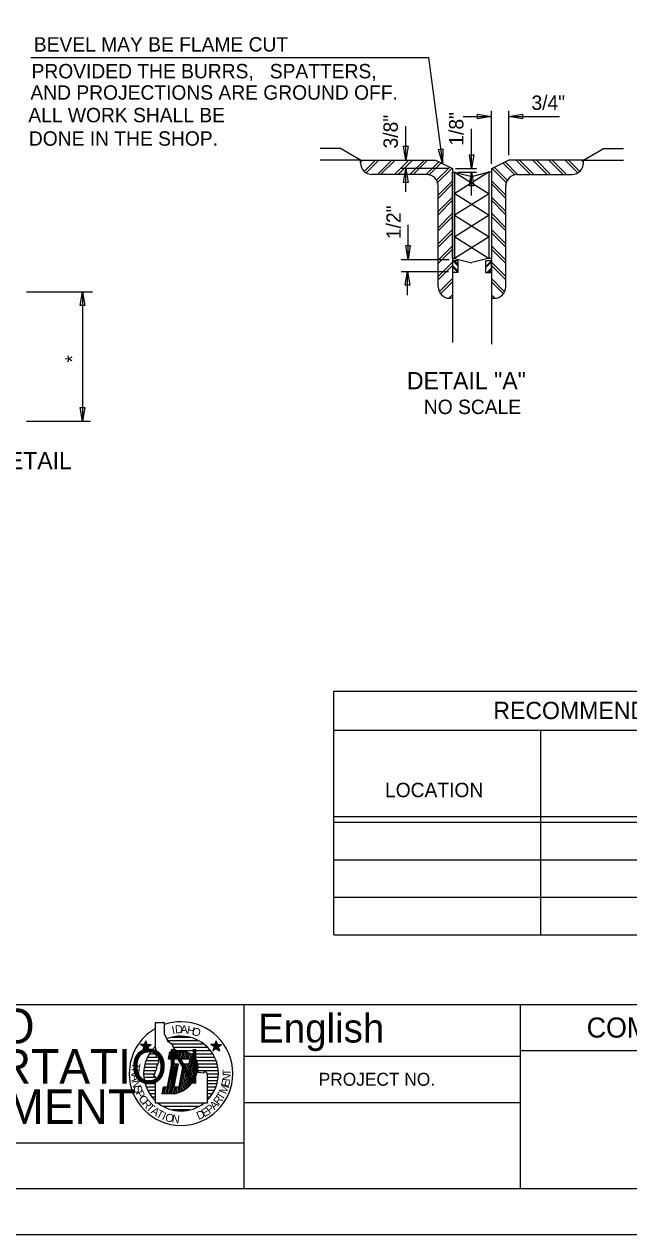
# Model space of a CAD drawing. Extents: x 0 to 11.3, y 0 to 7.9.
# Drawn here: x 5.619 to 7.81, y 0 to 4.38 of the extents above; entities that cross this region are included whole.
import ezdxf

# ---------------------------------------------------------------- set-up
doc = ezdxf.new("R2010")
doc.units = 0
for name, color, linetype in [('BORDER_ANNO_Cutsheet', 7, 'Continuous'), ('BRDG_ANNO_Anno-Sheet', 7, 'Continuous'), ('BRDG_ANNO_General-Notes', 7, 'Continuous'), ('BRDG_BASE_Obj-Line', 7, 'Continuous'), ('BRDG_BASE_Pattern', 7, 'Continuous')]:
    doc.layers.add(name, color=color, linetype=linetype)

msp = doc.modelspace()

# ---------------------------------------------------------------- linework, layer by layer
at = {"layer": 'BORDER_ANNO_Cutsheet'}
msp.add_lwpolyline([(0, 7.3333), (11.3333, 7.3333), (11.3333, 0), (0, 0)], close=True, dxfattribs=at)
at = {"layer": 'BRDG_ANNO_Anno-Sheet'}
for p, q in [((0.5, 0.8333), (6.4167, 0.8333)), ((6.4167, 0.1667), (6.4167, 0.8333)), ((6.4167, 0.8333), (11.1667, 0.8333)), ((7.4167, 0.1667), (7.4167, 0.8333)), ((6.0948, 0.6808), (6.0948, 0.7677)), ((6.0948, 0.7677), (6.1277, 0.7677)), ((6.1277, 0.7244), (6.1277, 0.7677)), ((6.0552, 0.6885), (6.0598, 0.7023)), ((6.0598, 0.6746), (6.0598, 0.7023)), ((6.0644, 0.6885), (6.0598, 0.7023)), ((6.1277, 0.7244), (6.1365, 0.7087)), ((6.1365, 0.7087), (6.1381, 0.7017)), ((6.1381, 0.7017), (6.1554, 0.6896)), ((6.139, 0.7027), (6.2502, 0.7027)), ((6.155, 0.7148), (6.2194, 0.7148)), ((6.3106, 0.6885), (6.3152, 0.7023)), ((6.3152, 0.6746), (6.3152, 0.7023)), ((6.3198, 0.6885), (6.3152, 0.7023)), ((6.0671, 0.68), (6.0408, 0.6885)), ((6.0552, 0.6885), (6.0408, 0.6885)), ((6.0525, 0.68), (6.0408, 0.6885)), ((6.0644, 0.6885), (6.0479, 0.666)), ((6.0525, 0.68), (6.0479, 0.666)), ((6.0598, 0.6746), (6.0479, 0.666)), ((6.0525, 0.68), (6.079, 0.6885)), ((6.0552, 0.6885), (6.0717, 0.666)), ((6.0598, 0.6746), (6.0717, 0.666)), ((6.0644, 0.6885), (6.079, 0.6885)), ((6.0671, 0.68), (6.079, 0.6885)), ((6.0671, 0.68), (6.0717, 0.666)), ((6.0806, 0.6669), (6.0979, 0.6669)), ((6.0915, 0.6787), (6.0954, 0.6787)), ((6.0981, 0.6687), (6.0948, 0.6808)), ((6.0981, 0.6583), (6.0981, 0.6687)), ((6.0981, 0.6496), (6.0981, 0.6583)), ((6.1417, 0.6356), (6.1469, 0.6619)), ((6.1465, 0.6356), (6.1513, 0.6619)), ((6.1469, 0.6619), (6.2042, 0.6619)), ((6.1517, 0.6356), (6.1567, 0.6619)), ((6.155, 0.6908), (6.269, 0.6908)), ((6.1554, 0.6896), (6.1608, 0.6756)), ((6.1571, 0.6356), (6.1619, 0.6619)), ((6.1596, 0.6787), (6.2835, 0.6787)), ((6.1608, 0.6756), (6.1781, 0.6619)), ((6.1623, 0.6356), (6.1673, 0.6619)), ((6.1675, 0.6356), (6.1725, 0.6619)), ((6.1719, 0.6669), (6.2942, 0.6669)), ((6.1729, 0.6356), (6.1777, 0.6619)), ((6.1781, 0.6356), (6.1831, 0.6619)), ((6.1835, 0.6356), (6.1883, 0.6619)), ((6.1887, 0.6356), (6.1937, 0.6619)), ((6.1942, 0.6356), (6.199, 0.6619)), ((6.1994, 0.6356), (6.2044, 0.6619)), ((6.2046, 0.6356), (6.2094, 0.6604)), ((6.21, 0.6356), (6.2144, 0.659)), ((6.3225, 0.68), (6.296, 0.6885)), ((6.3079, 0.68), (6.296, 0.6885)), ((6.3106, 0.6885), (6.296, 0.6885)), ((6.3198, 0.6885), (6.3033, 0.666)), ((6.3079, 0.68), (6.3033, 0.666)), ((6.3152, 0.6746), (6.3033, 0.666)), ((6.3079, 0.68), (6.3342, 0.6885)), ((6.3106, 0.6885), (6.3271, 0.666)), ((6.3152, 0.6746), (6.3271, 0.666)), ((6.3198, 0.6885), (6.3342, 0.6885)), ((6.3225, 0.68), (6.3342, 0.6885)), ((6.3225, 0.68), (6.3271, 0.666)), ((7.4167, 0.6667), (10.0833, 0.6667)), ((6.0569, 0.6188), (6.1037, 0.6188)), ((6.0604, 0.6308), (6.1063, 0.6308)), ((6.0656, 0.6427), (6.0994, 0.6427)), ((6.0723, 0.6548), (6.0975, 0.6548)), ((6.1, 0.6427), (6.0981, 0.6496)), ((6.1069, 0.6392), (6.1, 0.6427)), ((6.1, 0.6096), (6.1033, 0.6167)), ((6.1033, 0.6167), (6.1069, 0.6252)), ((6.1069, 0.6304), (6.1069, 0.6392)), ((6.1069, 0.6252), (6.1069, 0.6304)), ((6.1381, 0.535), (6.1537, 0.6183)), ((6.1387, 0.5106), (6.159, 0.6183)), ((6.2204, 0.6356), (6.1417, 0.6356)), ((6.1442, 0.5106), (6.1644, 0.6183)), ((6.1494, 0.5106), (6.1696, 0.6183)), ((6.1537, 0.6183), (6.1767, 0.6183)), ((6.1548, 0.5106), (6.175, 0.6183)), ((6.1767, 0.6183), (6.161, 0.535)), ((6.1812, 0.535), (6.1969, 0.6183)), ((6.1823, 0.5158), (6.2015, 0.6183)), ((6.1879, 0.5183), (6.2067, 0.6183)), ((6.1937, 0.521), (6.2121, 0.6183)), ((6.1969, 0.6183), (6.2173, 0.6183)), ((6.1998, 0.5248), (6.224, 0.654)), ((6.2058, 0.5285), (6.2287, 0.6506)), ((6.2121, 0.5335), (6.2331, 0.6462)), ((6.2152, 0.6356), (6.2192, 0.6567)), ((6.2173, 0.6183), (6.2204, 0.6356)), ((6.2185, 0.5396), (6.2375, 0.6415)), ((6.2229, 0.6548), (6.3025, 0.6548)), ((6.2252, 0.5467), (6.2417, 0.6354)), ((6.2323, 0.5563), (6.2456, 0.6273)), ((6.2367, 0.6427), (6.3092, 0.6427)), ((6.2406, 0.5725), (6.2485, 0.615)), ((6.2442, 0.6308), (6.3144, 0.6308)), ((6.2481, 0.6188), (6.3181, 0.6188)), ((6.4167, 0.6458), (7.4167, 0.6458)), ((6.0521, 0.5827), (6.0925, 0.5827)), ((6.0525, 0.5948), (6.0969, 0.5948)), ((6.0527, 0.5708), (6.0938, 0.5708)), ((6.0542, 0.6069), (6.0994, 0.6069)), ((6.0896, 0.575), (6.0929, 0.5835)), ((6.0948, 0.5698), (6.0896, 0.575)), ((6.0929, 0.5835), (6.0948, 0.5906)), ((6.0948, 0.5906), (6.1, 0.601)), ((6.0981, 0.5646), (6.0948, 0.5698)), ((6.1, 0.601), (6.1, 0.6096)), ((6.2469, 0.5925), (6.2494, 0.5887)), ((6.2475, 0.5948), (6.3225, 0.5948)), ((6.2492, 0.6069), (6.3208, 0.6069)), ((6.2494, 0.5887), (6.2598, 0.5871)), ((6.2598, 0.5871), (6.2702, 0.5854)), ((6.2702, 0.5854), (6.2754, 0.5923)), ((6.2754, 0.5923), (6.2823, 0.5819)), ((6.2817, 0.5827), (6.3229, 0.5827)), ((6.2823, 0.5819), (6.2823, 0.4758)), ((6.2825, 0.5708), (6.3223, 0.5708)), ((6.0544, 0.5587), (6.0994, 0.5587)), ((6.0571, 0.5469), (6.0946, 0.5469)), ((6.0612, 0.5348), (6.0942, 0.5348)), ((6.0948, 0.5506), (6.1, 0.5558)), ((6.0948, 0.4758), (6.0948, 0.5506)), ((6.1, 0.561), (6.0981, 0.5646)), ((6.1, 0.5558), (6.1, 0.561)), ((6.1198, 0.5106), (6.1244, 0.535)), ((6.1229, 0.5106), (6.1275, 0.535)), ((6.1244, 0.535), (6.1381, 0.535)), ((6.1283, 0.5106), (6.1329, 0.535)), ((6.1335, 0.5106), (6.1381, 0.535)), ((6.16, 0.5106), (6.1646, 0.535)), ((6.161, 0.535), (6.1812, 0.535)), ((6.1654, 0.5108), (6.17, 0.535)), ((6.171, 0.5123), (6.1752, 0.535)), ((6.1767, 0.514), (6.1804, 0.535)), ((6.2823, 0.5587), (6.3206, 0.5587)), ((6.2823, 0.5469), (6.3179, 0.5469)), ((6.2823, 0.5348), (6.3137, 0.5348)), ((6.0665, 0.5227), (6.0942, 0.5227)), ((6.0733, 0.5108), (6.0944, 0.5108)), ((6.0819, 0.4987), (6.0942, 0.4987)), ((6.0925, 0.4869), (6.0946, 0.4869)), ((6.1642, 0.5106), (6.1198, 0.5106)), ((6.2823, 0.5227), (6.3083, 0.5227)), ((6.2823, 0.5108), (6.3017, 0.5108)), ((6.2823, 0.4987), (6.2933, 0.4987)), ((6.2823, 0.4758), (6.0948, 0.4758)), ((6.2502, 0.4637), (6.124, 0.4637)), ((6.2196, 0.4519), (6.1558, 0.4519)), ((6.4167, 0.4792), (7.4167, 0.4792)), ((4.6667, 0.3333), (6.4167, 0.3333))]:
    msp.add_line(p, q, dxfattribs=at)
msp.add_lwpolyline([(0.5, 7.1667), (11.1667, 7.1667), (11.1667, 0.1667), (0.5, 0.1667)], close=True, dxfattribs=at)
for centre, radius, start, end in [((6.1875, 0.5833), 0.1875, 119.6331, 180), ((6.1875, 0.5833), 0.1875, 90, 108.596), ((6.1875, 0.5833), 0.1875, 0, 90), ((6.1875, 0.5833), 0.1354, 90, 112.1452), ((6.1875, 0.5833), 0.1354, 0, 90), ((6.1875, 0.5833), 0.1354, 133.1926, 180), ((6.1944, 0.608), 0.0547, 343.4981, 79.7362), ((6.1875, 0.5833), 0.1875, 180, 270), ((6.1875, 0.5833), 0.1354, 180.2644, 226.7946), ((6.145, 0.6127), 0.1039, 280.6479, 348.7719), ((6.1875, 0.5833), 0.1875, 270, 0), ((6.1875, 0.5833), 0.1354, 314.427, 0), ((6.1875, 0.5833), 0.1354, 232.5658, 270), ((6.1875, 0.5833), 0.1354, 270, 307.4536)]:
    msp.add_arc(centre, radius, start, end, dxfattribs=at)
at = {"layer": 'BRDG_ANNO_General-Notes'}
for p, q in [((5.6436, 4.2598), (7.0836, 4.2598)), ((7.0836, 4.2598), (7.1347, 3.878)), ((7.2101, 4.0467), (7.3117, 4.0467)), ((7.2617, 4.0384), (7.2617, 4.0551)), ((7.2617, 4.0551), (7.3117, 4.0467)), ((7.3117, 4.0467), (7.2617, 4.0384)), ((7.3117, 3.8745), (7.3117, 4.0671)), ((7.3744, 3.9059), (7.3744, 4.0671)), ((7.3744, 4.0467), (7.4244, 4.0551)), ((7.3744, 4.0467), (7.5586, 4.0467)), ((7.4244, 4.0384), (7.3744, 4.0467)), ((7.4244, 4.0551), (7.4244, 4.0384)), ((7.002, 3.8885), (7.002, 4.0116)), ((7.2403, 3.8577), (7.2403, 4.0012)), ((6.9937, 3.9385), (7.0104, 3.9385)), ((7.002, 3.8885), (6.9937, 3.9385)), ((7.0104, 3.9385), (7.002, 3.8885)), ((7.1198, 3.9265), (7.1363, 3.9287)), ((7.1347, 3.878), (7.1198, 3.9265)), ((7.1363, 3.9287), (7.1347, 3.878)), ((7.232, 3.9077), (7.2486, 3.9077)), ((7.2403, 3.8577), (7.232, 3.9077)), ((7.2486, 3.9077), (7.2403, 3.8577)), ((7.1535, 3.8577), (6.9847, 3.8577)), ((6.9937, 3.8077), (7.002, 3.8577)), ((7.002, 3.7738), (7.002, 3.8577)), ((7.002, 3.8577), (7.0104, 3.8077)), ((7.1818, 3.8577), (7.2577, 3.8577)), ((7.1897, 3.8451), (7.2577, 3.8451)), ((7.232, 3.7951), (7.2403, 3.8451)), ((7.2403, 3.76), (7.2403, 3.8451)), ((7.2403, 3.8451), (7.2486, 3.7951)), ((7.0104, 3.8077), (6.9937, 3.8077)), ((7.2486, 3.7951), (7.232, 3.7951)), ((7.0098, 3.529), (7.0098, 3.6537)), ((7.0015, 3.579), (7.0181, 3.579)), ((7.0098, 3.529), (7.0015, 3.579)), ((7.0181, 3.579), (7.0098, 3.529)), ((6.9852, 3.529), (7.1584, 3.529)), ((6.9852, 3.4854), (7.1568, 3.4854)), ((6.9999, 3.4354), (7.0082, 3.4854)), ((7.0082, 3.3992), (7.0082, 3.4854)), ((7.0082, 3.4854), (7.0166, 3.4354)), ((7.0166, 3.4354), (6.9999, 3.4354)), ((5.6277, 3.4122), (5.8667, 3.4122)), ((5.8219, 3.3622), (5.8303, 3.4122)), ((5.8303, 3.4122), (5.8303, 2.9434)), ((5.8303, 3.4122), (5.8386, 3.3622)), ((5.8386, 3.3622), (5.8219, 3.3622)), ((5.8219, 2.9934), (5.8386, 2.9934)), ((5.8303, 2.9434), (5.8219, 2.9934)), ((5.8386, 2.9934), (5.8303, 2.9434)), ((5.6277, 2.9434), (5.8601, 2.9434)), ((6.7408, 1.0856), (6.7408, 1.9669)), ((6.7408, 1.9669), (10.9133, 1.9669)), ((10.9133, 1.8245), (6.7408, 1.8245)), ((7.4908, 1.0856), (7.4908, 1.8245)), ((6.7408, 1.5129), (10.9133, 1.5129)), ((10.9133, 1.4921), (6.7408, 1.4921)), ((6.7408, 1.3565), (10.9133, 1.3565)), ((10.9133, 1.221), (6.7408, 1.221)), ((6.7408, 1.0856), (10.9133, 1.0856))]:
    msp.add_line(p, q, dxfattribs=at)
at = {"layer": 'BRDG_BASE_Obj-Line'}
for p, q in [((6.7647, 3.9302), (6.6918, 3.9302)), ((6.8376, 3.8885), (6.7647, 3.9302)), ((7.6451, 3.8885), (7.718, 3.9302)), ((7.718, 3.9302), (7.7907, 3.9302)), ((6.8376, 3.8885), (6.6918, 3.8885)), ((6.8376, 3.8885), (7.1092, 3.8885)), ((6.8376, 3.8781), (6.8376, 3.8885)), ((7.1092, 3.8885), (7.1709, 3.8577)), ((7.1709, 3.8577), (7.1709, 3.3886)), ((7.3744, 3.8885), (7.3117, 3.8572)), ((7.3117, 3.8572), (7.3117, 3.3886)), ((7.6451, 3.8885), (7.3744, 3.8885)), ((7.6451, 3.8885), (7.7907, 3.8885)), ((7.6451, 3.8781), (7.6451, 3.8885)), ((7.0772, 3.8365), (6.8793, 3.8365)), ((6.9418, 3.8365), (6.9418, 3.8365)), ((7.4055, 3.8365), (7.6034, 3.8365)), ((7.5409, 3.8365), (7.5409, 3.8365)), ((7.1189, 3.4303), (7.1189, 3.7948)), ((7.3638, 3.4303), (7.3638, 3.7948)), ((7.1189, 3.4927), (7.1189, 3.4927)), ((7.3638, 3.4927), (7.3638, 3.4927)), ((7.1709, 3.3886), (7.1605, 3.3886)), ((7.1709, 3.3886), (7.1709, 3.2281)), ((7.3117, 3.3886), (7.3117, 3.2229)), ((7.3117, 3.3886), (7.3221, 3.3886))]:
    msp.add_line(p, q, dxfattribs=at)
for points in [[(7.1709, 3.8451), (7.1787, 3.8451), (7.1787, 3.5326), (7.1709, 3.5326)], [(7.3039, 3.8455), (7.3117, 3.8455), (7.3117, 3.533), (7.3039, 3.533)], [(7.1709, 3.5243), (7.1709, 3.4827), (7.1917, 3.4827), (7.1917, 3.5243)], [(7.2909, 3.5239), (7.2909, 3.4822), (7.3117, 3.4822), (7.3117, 3.5239)]]:
    msp.add_lwpolyline(points, close=True, dxfattribs=at)
for centre, start, end in [((6.8793, 3.8781), 180, 270), ((7.6033, 3.8781), 270, 0), ((7.0772, 3.7948), 0, 90), ((7.4055, 3.7948), 90, 180), ((7.1605, 3.4302), 180, 270), ((7.3221, 3.4302), 270, 0)]:
    msp.add_arc(centre, 0.0417, start, end, dxfattribs=at)
at = {"layer": 'BRDG_BASE_Pattern'}
for p, q in [((7.0757, 3.8365), (7.121, 3.8818)), ((7.0864, 3.8354), (7.1294, 3.8784)), ((7.1134, 3.8153), (7.1603, 3.8622)), ((7.3692, 3.8153), (7.3228, 3.8617)), ((7.3962, 3.8354), (7.3534, 3.8782)), ((7.4069, 3.8365), (7.3614, 3.882)), ((7.1787, 3.8451), (7.2412, 3.8295)), ((7.1787, 3.8451), (7.3037, 3.767)), ((7.3039, 3.8455), (7.1789, 3.7673)), ((7.2412, 3.8297), (7.3039, 3.8455)), ((7.3037, 3.767), (7.1787, 3.6889)), ((7.1789, 3.7673), (7.3039, 3.6892)), ((7.1787, 3.6889), (7.3037, 3.6107)), ((7.3039, 3.6892), (7.1789, 3.6111)), ((7.3037, 3.6107), (7.1787, 3.5326)), ((7.1789, 3.6111), (7.3039, 3.533)), ((7.1787, 3.5326), (7.2412, 3.517)), ((7.3037, 3.5332), (7.2412, 3.5176))]:
    msp.add_line(p, q, dxfattribs=at)
for points in [[(6.8376, 3.8811), (6.8449, 3.8885)], [(6.851, 3.8474), (6.8921, 3.8885)], [(6.8577, 3.8424), (6.9039, 3.8885)], [(6.899, 3.8365), (6.951, 3.8885)], [(6.9107, 3.8365), (6.9628, 3.8885)], [(6.961, 3.8363), (7.0118, 3.8871)], [(6.9749, 3.8378), (7.0256, 3.8885)], [(7.018, 3.8378), (7.0689, 3.8885)], [(7.0305, 3.8384), (7.0806, 3.8885)], [(7.117, 3.807), (7.1686, 3.8587)], [(7.3657, 3.807), (7.3146, 3.8581)], [(7.4528, 3.8378), (7.402, 3.8885)], [(7.4659, 3.8365), (7.4138, 3.8885)], [(7.5141, 3.8365), (7.462, 3.8885)], [(7.5272, 3.8357), (7.4752, 3.8878)], [(7.5719, 3.8365), (7.5198, 3.8885)], [(7.5837, 3.8365), (7.5316, 3.8885)], [(7.6249, 3.8424), (7.5788, 3.8885)], [(7.6316, 3.8474), (7.5906, 3.8885)], [(7.6451, 3.8811), (7.6377, 3.8885)], [(7.1189, 3.7617), (7.1709, 3.8139)], [(7.3638, 3.7617), (7.3117, 3.8139)], [(7.1189, 3.7499), (7.1709, 3.8021)], [(7.3638, 3.7499), (7.3117, 3.8021)], [(7.1189, 3.7028), (7.1709, 3.7549)], [(7.1189, 3.691), (7.1709, 3.7431)], [(7.3638, 3.7028), (7.3117, 3.7549)], [(7.3638, 3.691), (7.3117, 3.7431)], [(7.1189, 3.644), (7.1709, 3.696)], [(7.1189, 3.6321), (7.1709, 3.6842)], [(7.3638, 3.644), (7.3117, 3.696)], [(7.3638, 3.6321), (7.3117, 3.6842)], [(7.1189, 3.585), (7.1709, 3.6371)], [(7.3638, 3.585), (7.3117, 3.6371)], [(7.1189, 3.5732), (7.1709, 3.6253)], [(7.3638, 3.5732), (7.3117, 3.6253)], [(7.1189, 3.526), (7.1709, 3.5781)], [(7.1189, 3.5143), (7.1709, 3.5664)], [(7.3638, 3.526), (7.3117, 3.5781)], [(7.3638, 3.5143), (7.3117, 3.5664)], [(7.1189, 3.4671), (7.1709, 3.5193)], [(7.1189, 3.4554), (7.1709, 3.5075)], [(7.1917, 3.4863), (7.1709, 3.5072)], [(7.1917, 3.5046), (7.172, 3.5243)], [(7.1917, 3.5112), (7.1786, 3.5243)], [(7.2909, 3.5026), (7.3114, 3.5231)], [(7.2909, 3.4982), (7.3115, 3.5189)], [(7.3638, 3.4671), (7.3117, 3.5193)], [(7.3638, 3.4554), (7.3117, 3.5075)], [(7.1903, 3.4827), (7.1709, 3.5021)], [(7.2961, 3.4822), (7.3114, 3.4975)], [(7.3023, 3.4822), (7.3114, 3.4912)], [(7.3597, 3.4123), (7.3117, 3.4604)], [(7.1229, 3.4123), (7.1698, 3.4593)], [(7.1274, 3.4051), (7.1709, 3.4485)], [(7.3552, 3.4051), (7.3117, 3.4485)], [(7.1582, 3.3887), (7.1709, 3.4014)], [(7.3244, 3.3887), (7.3117, 3.4014)]]:
    msp.add_lwpolyline(points, dxfattribs=at)

# ---------------------------------------------------------------- texts
at = {"layer": 'BRDG_ANNO_Anno-Sheet'}
for s, height, p in [('IDAHO', 0.125, (5.1279, 0.6927)), ('English', 0.10417, (6.4669, 0.6956)), ('COMPRESSION SEAL EXPANSION JOINT', 0.072709, (7.6569, 0.7135)), ('TRANSPORTATION', 0.125, (4.7156, 0.5469)), ('PROJECT NO.', 0.046875, (6.6864, 0.5392)), ('DEPARTMENT', 0.125, (4.8731, 0.401))]:
    msp.add_text(s, height=height, dxfattribs=at).set_placement(p)
for s, rotation, p in [('I', 11.9519, (6.1573, 0.726)), ('D', 5.2118, (6.1671, 0.7281)), ('A', 357.8718, (6.1856, 0.7294)), ('H', 349.6318, (6.2073, 0.7279)), ('O', 342.1917, (6.2248, 0.7244)), ('T', 259.4265, (6.0127, 0.6252)), ('R', 266.0275, (6.0088, 0.6025)), ('A', 273.764, (6.0077, 0.5802)), ('N', 83.1932, (6.365, 0.5544)), ('T', 90.4926, (6.3673, 0.5765)), ('N', 280.3758, (6.0096, 0.5571)), ('S', 287.9279, (6.0144, 0.5346)), ('M', 67.7139, (6.3502, 0.5069)), ('E', 75.6105, (6.3598, 0.5323)), ('P', 295.4976, (6.0219, 0.5135)), ('O', 302.6446, (6.0319, 0.4933)), ('R', 309.9079, (6.0446, 0.4742)), ('R', 52.3344, (6.3246, 0.4671)), ('T', 59.0362, (6.3379, 0.485)), ('T', 317.1211, (6.0592, 0.4571)), ('A', 324.6375, (6.076, 0.4419)), ('T', 331.7503, (6.0948, 0.429)), ('I', 337.0213, (6.1165, 0.4179)), ('O', 343.3287, (6.1275, 0.4135)), ('D', 22.9887, (6.251, 0.4152)), ('E', 30.5476, (6.2719, 0.4246)), ('P', 37.6656, (6.291, 0.4365)), ('A', 45, (6.3085, 0.4502)), ('N', 351.6598, (6.1529, 0.4067))]:
    msp.add_text(s, height=0.029, rotation=rotation, dxfattribs=at).set_placement(p)
at = {"layer": 'BRDG_ANNO_General-Notes'}
for s, height, p in [('BEVEL MAY BE FLAME CUT', 0.052083, (5.6544, 4.2812)), ('PROVIDED THE BURRS,   SPATTERS,', 0.052083, (5.6461, 4.1843)), ('AND PROJECTIONS ARE GROUND OFF.', 0.052083, (5.642, 4.1071)), ('3/4"', 0.05208, (7.457, 4.0702)), ('ALL WORK SHALL BE', 0.052083, (5.6345, 4.0253)), ('DONE IN THE SHOP.', 0.052083, (5.6365, 3.9406)), ('DETAIL "A"', 0.0625, (7.0057, 3.0591)), ('NO SCALE', 0.05208, (7.0671, 2.9696)), ('JOINT SEAL DETAIL', 0.0625, (4.9981, 2.7701)), ('RECOMMENDED MANUFACTURERS OF THE SHOWN JOINT ASSEMBLY', 0.0625, (7.3186, 1.866)), ('LOCATION', 0.05208, (6.9264, 1.5834))]:
    msp.add_text(s, height=height, dxfattribs=at).set_placement(p)
for s, height, p in [('3/8"', 0.05208, (6.9728, 3.9307)), ('1/8"', 0.05208, (7.2104, 3.9407)), ('1/2"', 0.05208, (6.9836, 3.6026)), ('*', 0.0521, (5.8199, 3.1557))]:
    msp.add_text(s, height=height, rotation=90, dxfattribs=at).set_placement(p)

doc.saveas('drawing.dxf')
